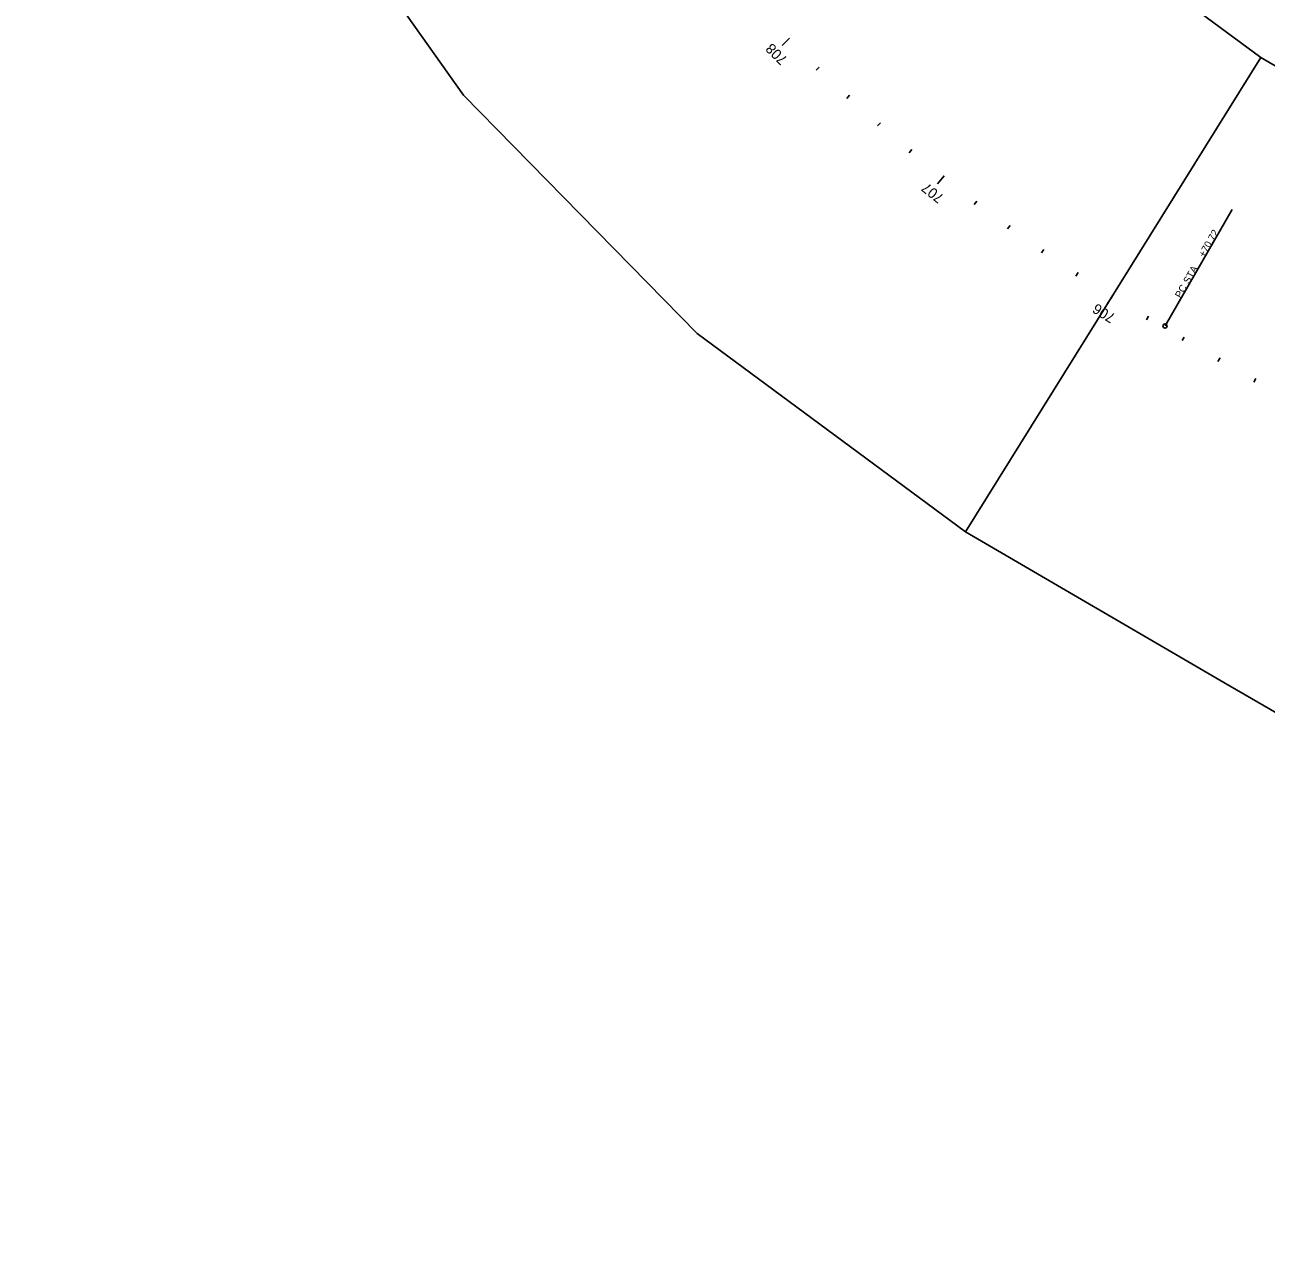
# Model space of a CAD drawing. Extents: x 2005522 to 2006988, y 402476 to 404900.
# Drawn here: x 2005788 to 2006388, y 402476 to 403074 of the extents above; entities that cross this region are included whole.
import ezdxf

# ---------------------------------------------------------------- set-up
doc = ezdxf.new("R2010")
doc.units = 0
for name, color, linetype in [('ClipDrawingBound_dp', 7, 'Continuous'), ('TextAlgnCardinalPnt', 7, 'Continuous'), ('TextAlgnStation100', 7, 'Continuous'), ('TextAlgnTicks100', 7, 'Continuous'), ('TextAlgnTicks1000', 7, 'Continuous'), ('TextAlgnTicks500', 7, 'Continuous')]:
    doc.layers.add(name, color=color, linetype=linetype)

msp = doc.modelspace()

# ---------------------------------------------------------------- linework, layer by layer
at = {"layer": 'ClipDrawingBound_dp'}
for points in [[(2006242.95, 402828.86), (2006385.68, 403058.05), (2006290.44, 403128.43), (2006207.54, 403213), (2006139.07, 403309.62), (2006086.75, 403415.85), (2006051.9, 403529.03), (2005788.36, 403470.3), (2005835.83, 403316.16), (2005907.08, 403171.48), (2006000.34, 403039.89), (2006113.24, 402924.71)], [(2006852.71, 402476.04), (2006987.75, 402709.84), (2006866.52, 402779.86), (2006745.28, 402849.88), (2006624.05, 402919.9), (2006502.82, 402989.92), (2006385.68, 403058.05), (2006242.95, 402828.86), (2006367.78, 402756.11), (2006489.01, 402686.09), (2006610.25, 402616.07), (2006731.48, 402546.06)]]:
    msp.add_lwpolyline(points, close=True, dxfattribs=at)
at = {"layer": 'TextAlgnCardinalPnt'}
msp.add_line((2006339.42, 402928.39), (2006371.93, 402984.68), dxfattribs=at)
msp.add_circle((2006339.42, 402928.39), 1, dxfattribs=at)
at = {"layer": 'TextAlgnTicks100'}
for p, q in [((2006157.95, 403067.46), (2006154.42, 403063.92)), ((2006172.27, 403053.5), (2006170.89, 403052.05)), ((2006186.9, 403039.87), (2006185.56, 403038.39)), ((2006201.84, 403026.57), (2006200.53, 403025.06)), ((2006217.08, 403013.62), (2006215.8, 403012.08)), ((2006232.61, 403001.01), (2006229.5, 402997.1)), ((2006248.42, 402988.77), (2006247.21, 402987.17)), ((2006264.5, 402976.88), (2006263.33, 402975.26)), ((2006280.85, 402965.36), (2006279.72, 402963.71)), ((2006297.46, 402954.22), (2006296.36, 402952.54)), ((2006314.31, 402943.45), (2006311.67, 402939.21)), ((2006331.41, 402933.07), (2006330.39, 402931.35)), ((2006348.7, 402923.03), (2006347.7, 402921.3)), ((2006366.02, 402913.03), (2006365.02, 402911.29)), ((2006383.34, 402903.02), (2006382.34, 402901.29))]:
    msp.add_line(p, q, dxfattribs=at)
at = {"layer": 'TextAlgnTicks1000'}
for p, q in [((2006157.95, 403067.46), (2006156.54, 403066.04)), ((2006314.31, 402943.45), (2006313.26, 402941.75))]:
    msp.add_line(p, q, dxfattribs=at)
at = {"layer": 'TextAlgnTicks500'}
for p, q in [((2006157.95, 403067.46), (2006156.54, 403066.04)), ((2006232.61, 403001.01), (2006231.37, 402999.45)), ((2006314.31, 402943.45), (2006313.26, 402941.75))]:
    msp.add_line(p, q, dxfattribs=at)

# ---------------------------------------------------------------- texts
at = {"layer": 'TextAlgnCardinalPnt'}
for s, p in [('+70.72', (2006358.4, 402961.26)), (' STA. ', (2006350.34, 402947.3)), ('PC', (2006347, 402941.52))]:
    msp.add_text(s, height=3.48, rotation=59.99111, dxfattribs=at).set_placement(p)
at = {"layer": 'TextAlgnStation100'}
for s, rotation, p in [('708', 135.08022, (2006157.29, 403057.53)), ('707', 141.58372, (2006233, 402991.13)), ('706', 148.08721, (2006315.87, 402933.65))]:
    msp.add_text(s, height=4.98, rotation=rotation, dxfattribs=at).set_placement(p)

doc.saveas('drawing.dxf')
